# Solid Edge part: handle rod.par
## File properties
Title: Handle Rod
Author: Abhinav Rai
Template: Normal.par
Last saved by: Robert a Rhodes jr
Revision: 6
Application: Solid Edge
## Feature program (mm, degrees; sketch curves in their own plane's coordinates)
sketch for "unnamed Protrusion 1" plane through (0, 0, 0) normal (0, -1, 0) x-axis (1, 0, 0)
  circle centre (0, 0) radius 3.9624
extrude "unnamed Protrusion 1" add finite 130.175 symmetric
sketch for "unnamed Cutout 1" plane through (0, 0, 0) normal (0, 0, 1) x-axis (1, 0, 0)
  circle centre (0, 57.4675) radius 1.905
extrude "unnamed Cutout 1" cut finite 101.6 symmetric
mirror "unnamed Mirror 1" of "unnamed Cutout 1"
pattern "unnamed Pattern 1"
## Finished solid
Body 1: solid body, 5 faces, 6 edges, 0 vertices.
  Faces by surface: cylinder 3, plane 2
  Edges by curve: intersection 4, circle 2
Bounding box of the edges (mm): 7.925 x 130.175 x 7.925, from (-3.9624, -65.0875, -3.9624) to (3.9624, 65.0875, 3.9624).
Cylindrical faces by radius (mm): R1.905 x2, R3.9624 x1
Planar faces by outward normal: +y 1, -y 1
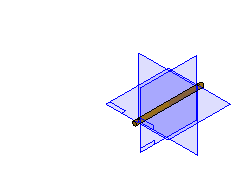
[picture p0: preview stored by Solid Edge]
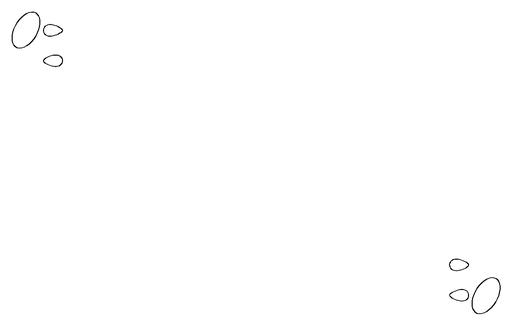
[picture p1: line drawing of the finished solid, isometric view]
